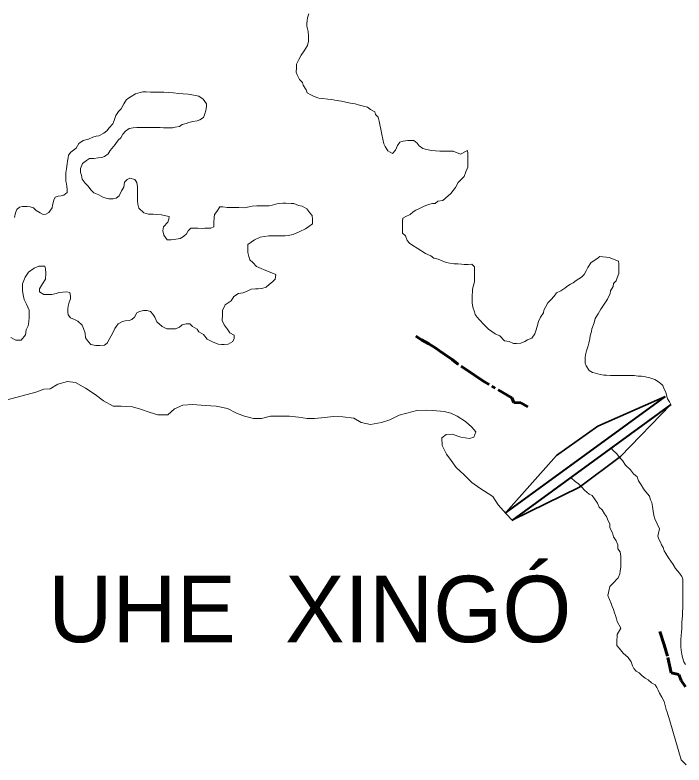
# Model space of a CAD drawing. Extents: x 553962 to 842807, y 8883888 to 9032388.
# Drawn here: x 628002 to 633037, y 8934087 to 8939733 of the extents above; entities that cross this region are included whole.
import ezdxf

# ---------------------------------------------------------------- set-up
doc = ezdxf.new("R2010")
doc.units = 0
doc.header["$LTSCALE"] = 20
doc.linetypes.add('LONG_DASH_SHORT_DASH', pattern=[9.9, 6, -1.2, 1.5, -1.2])
doc.layers.add('25', color=7, linetype='Continuous', lineweight=13)
doc.layers.add('7', color=7, linetype='LONG_DASH_SHORT_DASH', lineweight=60)
doc.layers.add('42', color=7, linetype='Continuous')

msp = doc.modelspace()

# ---------------------------------------------------------------- linework, layer by layer
at = {"layer": '25', "lineweight": 40}
for p, q in [((632895.32, 8936861.58), (631697.44, 8935987.07)), ((632938.96, 8936801.8), (631741.07, 8935927.3))]:
    msp.add_line(p, q, dxfattribs=at)
at = {"layer": '25'}
msp.add_line((631744.31, 8935929.66), (632938.96, 8936801.8), dxfattribs=at)
for points in [[(631355.09, 8938684.92), (631300.24, 8938707.82), (631267.72, 8938708.03), (631247.71, 8938708.16), (631220.21, 8938708.34), (631200.2, 8938708.48), (631167.71, 8938711.19), (631137.71, 8938713.89), (631100.25, 8938721.65), (631070.3, 8938729.36), (631042.92, 8938747.07), (631028.07, 8938767.19), (631003.21, 8938787.39), (630958.2, 8938787.69), (630923.14, 8938782.91), (630898.08, 8938775.57), (630880.38, 8938750.65), (630865.11, 8938715.7), (630842.41, 8938690.82), (630807.54, 8938711.07), (630787.78, 8938743.75), (630777.93, 8938763.84), (630770.7, 8938798.94), (630763.46, 8938834.03), (630756.26, 8938874.14), (630751.43, 8938896.7), (630741.71, 8938934.32), (630734.44, 8938964.41), (630714.58, 8938984.57), (630709.73, 8939004.63), (630677.36, 8939022.37), (630654.98, 8939040.05), (630625.03, 8939047.75), (630595.07, 8939055.46), (630562.62, 8939063.19), (630527.64, 8939068.42), (630492.68, 8939076.17), (630460.23, 8939083.89), (630410.27, 8939091.73), (630385.29, 8939096.9), (630355.3, 8939099.61), (630317.82, 8939104.86), (630287.83, 8939107.57), (630252.91, 8939120.32), (630228, 8939132.99), (630200.6, 8939148.2), (630193.27, 8939170.78), (630171.03, 8939205.98), (630166.18, 8939226.03), (630143.84, 8939248.71), (630126.6, 8939283.88), (630119.25, 8939303.96), (630119.5, 8939336.5), (630119.71, 8939364.04), (630137.48, 8939398.97), (630155.23, 8939431.4), (630177.99, 8939463.79), (630203.31, 8939503.68), (630211.06, 8939536.17), (630211.35, 8939573.73), (630209.11, 8939608.79), (630204.26, 8939628.85), (630199.41, 8939648.91), (630199.56, 8939668.94), (630199.73, 8939691.47), (630202.39, 8939711.48), (630212.62, 8939741.46)], [(627997.49, 8938208.93), (628005.26, 8938243.93), (628015.45, 8938268.9), (628035.6, 8938286.29), (628058.14, 8938291.15), (628093.15, 8938290.91), (628115.64, 8938288.26), (628140.6, 8938280.58), (628160.45, 8938260.42), (628190.33, 8938242.71), (628212.77, 8938232.54), (628232.79, 8938234.91), (628255.39, 8938247.28), (628280.67, 8938282.16), (628283.33, 8938302.17), (628293.62, 8938339.66), (628303.79, 8938362.12), (628326.36, 8938369.48), (628348.88, 8938371.84), (628368.93, 8938376.71), (628394.09, 8938396.57), (628394.26, 8938419.1), (628391.93, 8938441.65), (628389.59, 8938461.69), (628384.73, 8938481.76), (628384.89, 8938501.78), (628385.06, 8938524.31), (628385.21, 8938544.34), (628390.44, 8938574.35), (628393.23, 8938611.88), (628395.88, 8938631.89), (628401.07, 8938656.89), (628403.73, 8938676.9), (628421.4, 8938699.32), (628441.55, 8938716.71), (628461.67, 8938731.6), (628481.94, 8938766.51), (628514.63, 8938788.83), (628534.67, 8938793.71), (628554.72, 8938798.58), (628587.35, 8938813.39), (628612.41, 8938820.73), (628632.44, 8938823.1), (628670.11, 8938842.88), (628692.75, 8938860.25), (628710.43, 8938882.67), (628738.19, 8938915.03), (628748.38, 8938940), (628761.17, 8938977.47), (628781.41, 8939007.38), (628801.57, 8939027.27), (628821.86, 8939064.69), (628842.11, 8939097.1), (628877.3, 8939119.4), (628907.47, 8939139.23), (628942.55, 8939149.01), (628965.1, 8939153.87), (628990.11, 8939153.7), (629022.63, 8939153.49), (629062.64, 8939153.23), (629097.65, 8939152.99), (629122.66, 8939152.83), (629157.66, 8939150.09), (629195.15, 8939147.34), (629232.63, 8939142.08), (629267.62, 8939139.35), (629305.12, 8939136.6), (629347.58, 8939128.81), (629385.04, 8939121.05), (629417.38, 8939098.3), (629442.14, 8939065.59), (629441.99, 8939045.57), (629439.24, 8939013.04), (629431.55, 8938988.05), (629421.33, 8938960.58), (629393.69, 8938943.24), (629373.62, 8938935.86), (629341.07, 8938931.07), (629311, 8938923.76), (629290.94, 8938916.38), (629260.87, 8938909.07), (629240.75, 8938894.18), (629208.2, 8938889.39), (629188.15, 8938884.52), (629155.64, 8938884.73), (629120.63, 8938884.96), (629093.12, 8938885.15), (629060.6, 8938885.36), (629030.59, 8938885.56), (629010.58, 8938885.69), (628978.07, 8938885.91)], [(628978.07, 8938885.91), (628945.56, 8938886.12), (628918.05, 8938886.3), (628890.51, 8938883.98), (628860.47, 8938879.17), (628832.8, 8938859.33), (628812.62, 8938836.93), (628797.41, 8938809.49), (628777.27, 8938792.1), (628754.49, 8938757.2), (628719.13, 8938712.37), (628703.94, 8938687.44), (628676.27, 8938667.59), (628656.21, 8938660.21), (628628.68, 8938657.89), (628596.13, 8938653.1), (628563.62, 8938653.32), (628541, 8938638.44), (628510.81, 8938616.11), (628495.52, 8938578.66), (628495.29, 8938548.62), (628502.64, 8938528.54), (628507.42, 8938498.47), (628529.7, 8938468.28), (628549.55, 8938448.12), (628574.31, 8938415.41), (628594.17, 8938395.25), (628631.57, 8938379.98), (628668.93, 8938359.71), (628708.87, 8938349.43), (628741.39, 8938349.21), (628763.93, 8938354.07), (628786.57, 8938371.44), (628804.37, 8938408.88), (628822.08, 8938436.3), (628824.87, 8938473.84), (628845.03, 8938493.73), (628865.11, 8938503.61), (628902.57, 8938495.85), (628919.9, 8938473.21), (628924.66, 8938440.63), (628924.51, 8938420.6), (628924.3, 8938393.07), (628924.07, 8938363.03), (628923.84, 8938332.98), (628926.15, 8938307.93), (628933.42, 8938277.84), (628970.69, 8938245.05), (629005.63, 8938234.81), (629040.64, 8938234.58), (629063.13, 8938231.92), (629103.13, 8938229.15), (629125.6, 8938224), (629163.06, 8938216.24), (629160.4, 8938196.23), (629152.73, 8938173.75), (629119.95, 8938138.92), (629114.72, 8938108.91), (629121.98, 8938076.32), (629146.72, 8938041.1), (629176.73, 8938040.9), (629196.76, 8938043.27), (629244.33, 8938050.47), (629269.46, 8938065.32), (629292.12, 8938085.2), (629304.79, 8938107.65), (629324.96, 8938127.55), (629347.46, 8938127.39), (629377.48, 8938127.2), (629409.99, 8938126.98), (629430.02, 8938129.35), (629475.03, 8938129.05), (629497.62, 8938138.92), (629497.88, 8938173.97), (629500.65, 8938209), (629503.32, 8938231.51), (629521, 8938253.92), (629543.78, 8938288.83), (629566.29, 8938288.68), (629598.76, 8938283.46), (629621.27, 8938283.31), (629656.28, 8938283.08), (629686.29, 8938282.88), (629728.81, 8938282.6), (629763.88, 8938289.87), (629786.43, 8938294.73), (629821.46, 8938297), (629856.47, 8938296.77), (629876.48, 8938296.64), (629914, 8938296.39), (629936.54, 8938301.25), (629971.63, 8938311.03), (630016.69, 8938315.74), (630039.2, 8938315.59), (630079.21, 8938315.33), (630099.22, 8938315.19), (630136.62, 8938299.92), (630164.1, 8938294.74), (630198.96, 8938274.48), (630221.24, 8938244.29), (630238.59, 8938224.14)], [(631394.09, 8938551.97), (631409.37, 8938586.92), (631409.63, 8938621.97), (631409.88, 8938654.51), (631410.17, 8938692.06), (631407.82, 8938712.11), (631355.09, 8938684.92)], [(632474.66, 8937906.42), (632404.69, 8937914.4), (632382.05, 8937897.02), (632361.95, 8937884.64), (632336.8, 8937867.28), (632314.03, 8937832.38), (632301.33, 8937807.43), (632286.12, 8937779.99), (632265.96, 8937760.1), (632245.85, 8937747.71), (632225.75, 8937735.33), (632203.11, 8937717.95), (632183.02, 8937708.07), (632162.9, 8937693.18), (632140.26, 8937675.81), (632110.1, 8937655.98), (632077.47, 8937641.17), (632059.77, 8937616.26), (632034.55, 8937588.89), (632011.87, 8937566.5), (631994.12, 8937534.07), (631981.44, 8937511.62), (631978.79, 8937491.62), (631956.03, 8937459.22), (631943.28, 8937426.76), (631935.57, 8937399.27), (631925.29, 8937364.29), (631915.04, 8937331.81), (631892.29, 8937299.41), (631859.68, 8937287.11), (631839.58, 8937274.73), (631809.47, 8937262.41), (631776.94, 8937260.12), (631754.43, 8937260.27), (631722.03, 8937275.51), (631687.05, 8937280.74), (631649.83, 8937318.55), (631614.93, 8937333.8), (631565.17, 8937369.17), (631530.43, 8937404.46), (631498.16, 8937437.21), (631480.81, 8937457.36), (631465.95, 8937477.48), (631461.11, 8937497.54), (631448.87, 8937532.67), (631441.61, 8937565.26), (631441.76, 8937585.3), (631441.92, 8937605.32), (631442.07, 8937625.35), (631444.74, 8937647.86), (631444.89, 8937667.89), (631450.07, 8937690.39), (631460.34, 8937725.37), (631460.66, 8937767.93), (631460.89, 8937797.97), (631461.2, 8937838.02), (631441.34, 8937858.18), (631413.81, 8937855.86), (631383.79, 8937856.06), (631361.29, 8937856.21), (631333.79, 8937858.89), (631306.29, 8937859.08), (631273.81, 8937864.3), (631246.34, 8937869.49), (631216.42, 8937882.2), (631186.51, 8937894.92), (631154.05, 8937902.64), (631131.67, 8937920.32), (631091.79, 8937938.1), (631056.95, 8937960.87), (631029.57, 8937978.57), (630997.21, 8937998.82), (630972.33, 8938016.5), (630952.48, 8938036.66), (630940.24, 8938071.8), (630917.88, 8938091.97), (630918.15, 8938127.02), (630918.42, 8938162.07), (630918.57, 8938182.09), (630921.24, 8938204.61), (630943.85, 8938216.98), (630976.48, 8938231.78), (630999.13, 8938251.66), (631019.24, 8938264.04), (631046.84, 8938276.38), (631081.99, 8938293.67), (631102.06, 8938301.05), (631124.62, 8938308.41), (631144.67, 8938313.28), (631164.68, 8938313.15), (631184.82, 8938330.54), (631222.39, 8938337.8), (631242.53, 8938355.19), (631262.67, 8938372.59), (631282.81, 8938389.98), (631300.49, 8938412.39), (631318.17, 8938434.81), (631338.46, 8938472.23), (631361.14, 8938494.61), (631381.32, 8938517.01), (631394.09, 8938551.97)], [(630238.59, 8938224.14), (630240.87, 8938194.09), (630240.62, 8938161.54), (630212.96, 8938141.7), (630187.81, 8938124.34), (630145.14, 8938104.59), (630094.93, 8938079.89), (630057.36, 8938072.63), (630034.83, 8938070.27), (630004.82, 8938070.47), (629969.81, 8938070.71), (629937.29, 8938070.92), (629912.29, 8938071.08), (629879.73, 8938066.3), (629847.18, 8938061.5), (629804.51, 8938041.76), (629754.21, 8938004.54), (629753.94, 8937969.49), (629753.75, 8937944.46), (629761.03, 8937914.36), (629768.34, 8937889.28), (629790.7, 8937869.1), (629820.48, 8937838.86), (629855.38, 8937823.61), (629877.83, 8937815.95), (629922.71, 8937798.13), (629965.1, 8937780.33), (629959.83, 8937745.31), (629939.67, 8937725.42), (629917.03, 8937708.04), (629891.82, 8937683.17), (629859.24, 8937673.37), (629831.71, 8937671.05), (629811.7, 8937671.19), (629779.17, 8937668.9), (629754.06, 8937656.55), (629718.94, 8937641.76), (629683.88, 8937636.98), (629648.7, 8937614.68), (629628.44, 8937582.27), (629583.2, 8937552.53), (629562.84, 8937507.6), (629562.6, 8937475.05), (629562.27, 8937432.5), (629577.03, 8937399.85), (629599.31, 8937369.66), (629619.09, 8937339.49), (629651.47, 8937321.75), (629651.28, 8937296.72), (629641.1, 8937274.25), (629605.94, 8937254.46), (629575.91, 8937252.15), (629555.9, 8937252.28), (629530.91, 8937254.96), (629488.53, 8937272.76), (629448.66, 8937293.05), (629421.42, 8937328.28), (629386.56, 8937348.54), (629371.71, 8937368.67), (629336.84, 8937388.92), (629316.99, 8937409.08), (629289.48, 8937409.27), (629259.41, 8937401.96), (629239.25, 8937382.06), (629209.14, 8937369.74), (629176.63, 8937369.96), (629144.12, 8937370.17), (629109.24, 8937387.93), (629069.49, 8937423.24), (629054.75, 8937458.39), (629039.91, 8937481.01), (629022.56, 8937501.16), (628997.61, 8937508.83), (628970.1, 8937509.02), (628940.03, 8937501.71), (628919.94, 8937491.82), (628902.19, 8937459.4), (628882.05, 8937442), (628861.96, 8937432.12), (628831.94, 8937429.82), (628811.89, 8937424.94), (628779.24, 8937407.64), (628753.96, 8937372.75), (628736.17, 8937335.32), (628715.89, 8937300.4), (628695.6, 8937262.98), (628675.48, 8937248.1), (628640.45, 8937245.82), (628610.44, 8937246.02), (628572.98, 8937253.78), (628555.63, 8937273.92), (628533.35, 8937304.11), (628528.61, 8937339.19), (628516.37, 8937374.33), (628506.56, 8937399.42), (628474.25, 8937427.18), (628449.34, 8937439.86), (628419.42, 8937452.58), (628402.09, 8937475.22), (628399.76, 8937497.77), (628399.93, 8937520.3)], [(632938.96, 8936801.8), (632929.11, 8936821.89), (632914.28, 8936844.52), (632904.48, 8936872.12), (632899.65, 8936894.69), (632887.32, 8936917.3), (632877.52, 8936944.9), (632852.69, 8936967.6), (632817.85, 8936990.36), (632780.41, 8937000.63), (632747.95, 8937008.35), (632717.98, 8937013.56), (632692.97, 8937013.72), (632662.99, 8937018.92), (632632.98, 8937019.12), (632612.97, 8937019.26), (632585.46, 8937019.44), (632557.95, 8937019.62), (632527.94, 8937019.82), (632502.93, 8937019.99), (632482.92, 8937020.12), (632452.93, 8937022.82), (632432.92, 8937022.96), (632405.43, 8937025.64), (632370.49, 8937035.89), (632348.02, 8937041.04), (632323.13, 8937056.23), (632300.88, 8937091.42), (632293.54, 8937111.5), (632293.69, 8937131.53), (632293.86, 8937154.06), (632296.51, 8937174.07), (632304.24, 8937204.06), (632317.03, 8937241.53), (632319.69, 8937261.54), (632327.46, 8937296.53), (632330.13, 8937319.05), (632340.38, 8937351.53), (632343.03, 8937371.54), (632360.88, 8937416.48), (632368.63, 8937448.98), (632391.41, 8937483.88), (632411.69, 8937518.79), (632442.04, 8937563.65), (632462.28, 8937593.56), (632482.61, 8937635.99), (632485.26, 8937656), (632503.02, 8937688.43), (632505.69, 8937710.94), (632525.85, 8937730.84), (632533.52, 8937753.32), (632546.29, 8937788.28), (632546.52, 8937818.32), (632546.69, 8937840.85), (632546.84, 8937860.88), (632544.5, 8937880.92), (632474.66, 8937906.42)], [(628399.93, 8937520.3), (628402.58, 8937540.31), (628410.31, 8937570.3), (628420.51, 8937595.27), (628420.66, 8937615.3), (628413.39, 8937645.39), (628390.9, 8937648.04), (628360.87, 8937645.73), (628333.34, 8937643.41), (628310.77, 8937636.05), (628278.2, 8937628.76), (628255.69, 8937628.9), (628218.18, 8937629.15), (628185.82, 8937649.39), (628185.99, 8937671.92), (628208.79, 8937709.33), (628231.55, 8937744.23), (628234.4, 8937789.27), (628232.15, 8937821.83), (628227.3, 8937841.89), (628207.29, 8937842.03), (628182.28, 8937842.19), (628147.15, 8937827.4), (628104.41, 8937797.64), (628079.11, 8937760.26), (628058.73, 8937710.32), (628058.35, 8937660.25), (628063.1, 8937627.68), (628070.34, 8937592.58), (628087.57, 8937557.42), (628107.24, 8937512.22), (628109.49, 8937479.66), (628109.34, 8937459.63), (628106.55, 8937422.1), (628101.32, 8937392.09), (628086.09, 8937362.15), (628080.8, 8937324.63), (628047.98, 8937284.79), (628027.97, 8937284.92), (628007.97, 8937285.06), (627970.61, 8937305.33)], [(627021.94, 8936878.5), (627718.79, 8936757.52), (627790.66, 8936796.37), (628157.56, 8936893.08), (628217.99, 8936915.41), (628265.54, 8936920.17), (628323.25, 8936954.9), (628395.89, 8936974.54), (628455.89, 8936966.72)], [(628455.89, 8936966.72), (628533.22, 8936923.79), (628605.53, 8936875.87), (628667.83, 8936828.01), (628740.17, 8936787.6), (628800.21, 8936787.29), (628885.25, 8936784.35), (628945.2, 8936766.52), (629020.12, 8936741.11), (629077.56, 8936723.3), (629152.61, 8936722.91), (629202.86, 8936767.69), (629265.96, 8936795.72), (629337.8, 8936802.11), (629403.26, 8936795.72), (629434.61, 8936792.36), (629514.64, 8936789.45), (629602.11, 8936771.48), (629669.47, 8936736.1), (629729.4, 8936713.27), (629796.85, 8936695.41), (629856.89, 8936695.09), (629924.52, 8936712.26), (629997.07, 8936714.38), (630067.11, 8936714.02), (630134.62, 8936706.16), (630199.61, 8936695.82), (630257.14, 8936695.52), (630334.73, 8936702.62), (630397.3, 8936709.8), (630469.85, 8936709.43), (630552.35, 8936698.99), (630607.22, 8936666.18), (630677.19, 8936650.8), (630759.81, 8936665.39), (630822.45, 8936685.08), (630892.67, 8936719.74), (630950.29, 8936736.96), (631025.43, 8936756.58), (631097.99, 8936758.71), (631145.51, 8936755.96), (631233.03, 8936748), (631282.99, 8936735.23), (631330.37, 8936712.48), (631393.79, 8936673.48), (631440.13, 8936630.98), (631470.01, 8936595.15), (631454.78, 8936554.03), (631422.14, 8936544.35), (631357.15, 8936554.7), (631291.34, 8936578.41), (631247.43, 8936575.97), (631214.54, 8936550.43), (631216.75, 8936492.87), (631248.95, 8936427.65), (631283.74, 8936379.93), (631323.5, 8936327.18), (631383.27, 8936271.82), (631440.13, 8936212.95), (631440.13, 8936212.95), (631499.89, 8936171.15), (631597.59, 8936108.07), (631637.31, 8936045.32), (631699.51, 8935977.44), (631744.31, 8935929.66)], [(632498.49, 8935450.3), (632541.35, 8935495.08), (632554.1, 8935527.54), (632556.76, 8935547.55), (632562.01, 8935580.07), (632562.22, 8935607.6), (632562.39, 8935630.13), (632562.6, 8935657.67), (632557.86, 8935692.75), (632538.03, 8935715.41), (632538.25, 8935745.46), (632525.98, 8935775.58), (632506.2, 8935805.75), (632498.93, 8935835.84), (632479.2, 8935873.53), (632479.43, 8935903.57), (632467.1, 8935926.18), (632454.84, 8935958.81), (632439.99, 8935978.93), (632420.21, 8936009.11), (632397.85, 8936029.28), (632385.58, 8936059.41), (632363.31, 8936092.1), (632345.98, 8936114.75), (632323.55, 8936124.91), (632288.76, 8936155.18), (632268.92, 8936177.85), (632244.11, 8936203.05), (632219.23, 8936220.73), (632189.41, 8936245.96), (632184.84, 8936251.26), (632488.34, 8936472.82)], [(632488.34, 8936472.82), (632503.63, 8936454.18), (632528.47, 8936431.49), (632553.23, 8936398.78), (632575.59, 8936378.6), (632597.83, 8936343.4), (632635.07, 8936308.11), (632657.36, 8936277.92), (632684.71, 8936257.71), (632694.49, 8936227.6), (632714.27, 8936197.43), (632731.55, 8936167.27), (632748.88, 8936144.63), (632778.65, 8936111.89), (632785.94, 8936084.3), (632795.79, 8936064.2), (632800.57, 8936034.13), (632805.3, 8935999.05), (632810.06, 8935966.47), (632817.37, 8935941.39), (632851.81, 8935866.05), (632841.39, 8935811.05), (632848.72, 8935788.46), (632861.05, 8935765.85), (632868.4, 8935745.78), (632880.75, 8935725.66), (632888.07, 8935700.58), (632900.42, 8935680.47)], [(632900.42, 8935680.47), (632920.18, 8935647.8), (632937.5, 8935622.64), (632954.81, 8935597.49), (632972.09, 8935567.34), (633004.34, 8935532.08), (633021.65, 8935506.92), (633029, 8935486.85), (633028.76, 8935454.31), (633028.36, 8935401.73), (633028.13, 8935371.69), (633027.97, 8935351.66), (633027.75, 8935321.62), (633027.54, 8935294.09), (633027.31, 8935264.05), (633027.16, 8935244.02), (633026.91, 8935211.48), (633024.2, 8935183.95), (633021.53, 8935161.44), (633021.36, 8935138.91), (633021.18, 8935116.38), (633018.44, 8935083.85), (633015.78, 8935063.84), (633013.01, 8935028.81), (633012.84, 8935006.28), (633012.61, 8934976.24), (633014.93, 8934951.19), (633022.2, 8934921.1), (633027.01, 8934896.03), (633036.77, 8934863.42), (633049.12, 8934843.31)], [(633053.37, 8934087.21), (633016.14, 8934125.01), (632930.84, 8934418.49), (632911.33, 8934483.71), (632903.97, 8934503.79), (632896.7, 8934533.88), (632886.93, 8934563.98), (632869.66, 8934596.65), (632852.39, 8934626.8), (632842.55, 8934649.4), (632832.7, 8934669.49), (632820.35, 8934689.6), (632792.95, 8934704.81), (632768.12, 8934727.5), (632745.7, 8934740.17), (632723.32, 8934757.84), (632700.99, 8934780.52), (632676.08, 8934793.2), (632658.72, 8934813.35), (632648.87, 8934833.44), (632639.09, 8934863.55), (632616.83, 8934896.24), (632579.56, 8934929.03), (632549.84, 8934966.78), (632532.48, 8934986.92), (632532.64, 8935006.95), (632532.81, 8935029.48), (632532.96, 8935049.51), (632533.11, 8935069.54), (632560.98, 8935116.92), (632533.86, 8935167.17), (632529.01, 8935187.23), (632521.69, 8935212.32), (632514.34, 8935232.39), (632507.03, 8935257.48), (632497.2, 8935280.07), (632489.87, 8935302.65), (632462.81, 8935362.92), (632478.33, 8935430.4), (632498.49, 8935450.3)]]:
    msp.add_lwpolyline(points, dxfattribs=at)
at = {"layer": '25', "lineweight": 35}
for points in [[(631697.44, 8935987.07), (632077.48, 8936416.15), (632389.24, 8936639.11), (632895.32, 8936861.58)], [(631744.31, 8935929.66), (632251.25, 8936178.6), (632559.18, 8936408.68), (632938.96, 8936801.8)]]:
    msp.add_lwpolyline(points, dxfattribs=at)
at = {"layer": '7'}
for points in [[(631168.26, 8937224.28), (631115.98, 8937257.08), (631061.19, 8937287.4), (631019.28, 8937316.45)], [(631862.91, 8936784.11), (631808, 8936813), (631755.52, 8936815.78), (631740.76, 8936850.9), (631531.59, 8936974.62), (631459.41, 8937022.55), (631332.49, 8937108.3), (631292.69, 8937138.54), (631237.94, 8937176.36), (631198.13, 8937204.1), (631168.26, 8937224.28)], [(633048.61, 8934674.4), (633016.43, 8934722.12), (632999.23, 8934767.25), (632941.82, 8934780.07), (632912.66, 8934905.34), (632888.25, 8934993.06), (632856.43, 8935093.32)]]:
    msp.add_lwpolyline(points, dxfattribs=at)

# ---------------------------------------------------------------- texts
at = {"layer": '42'}
msp.add_text('UHE  XINGÓ', height=500, dxfattribs=at).set_placement((628251.94, 8935011.64))

doc.saveas('drawing.dxf')
